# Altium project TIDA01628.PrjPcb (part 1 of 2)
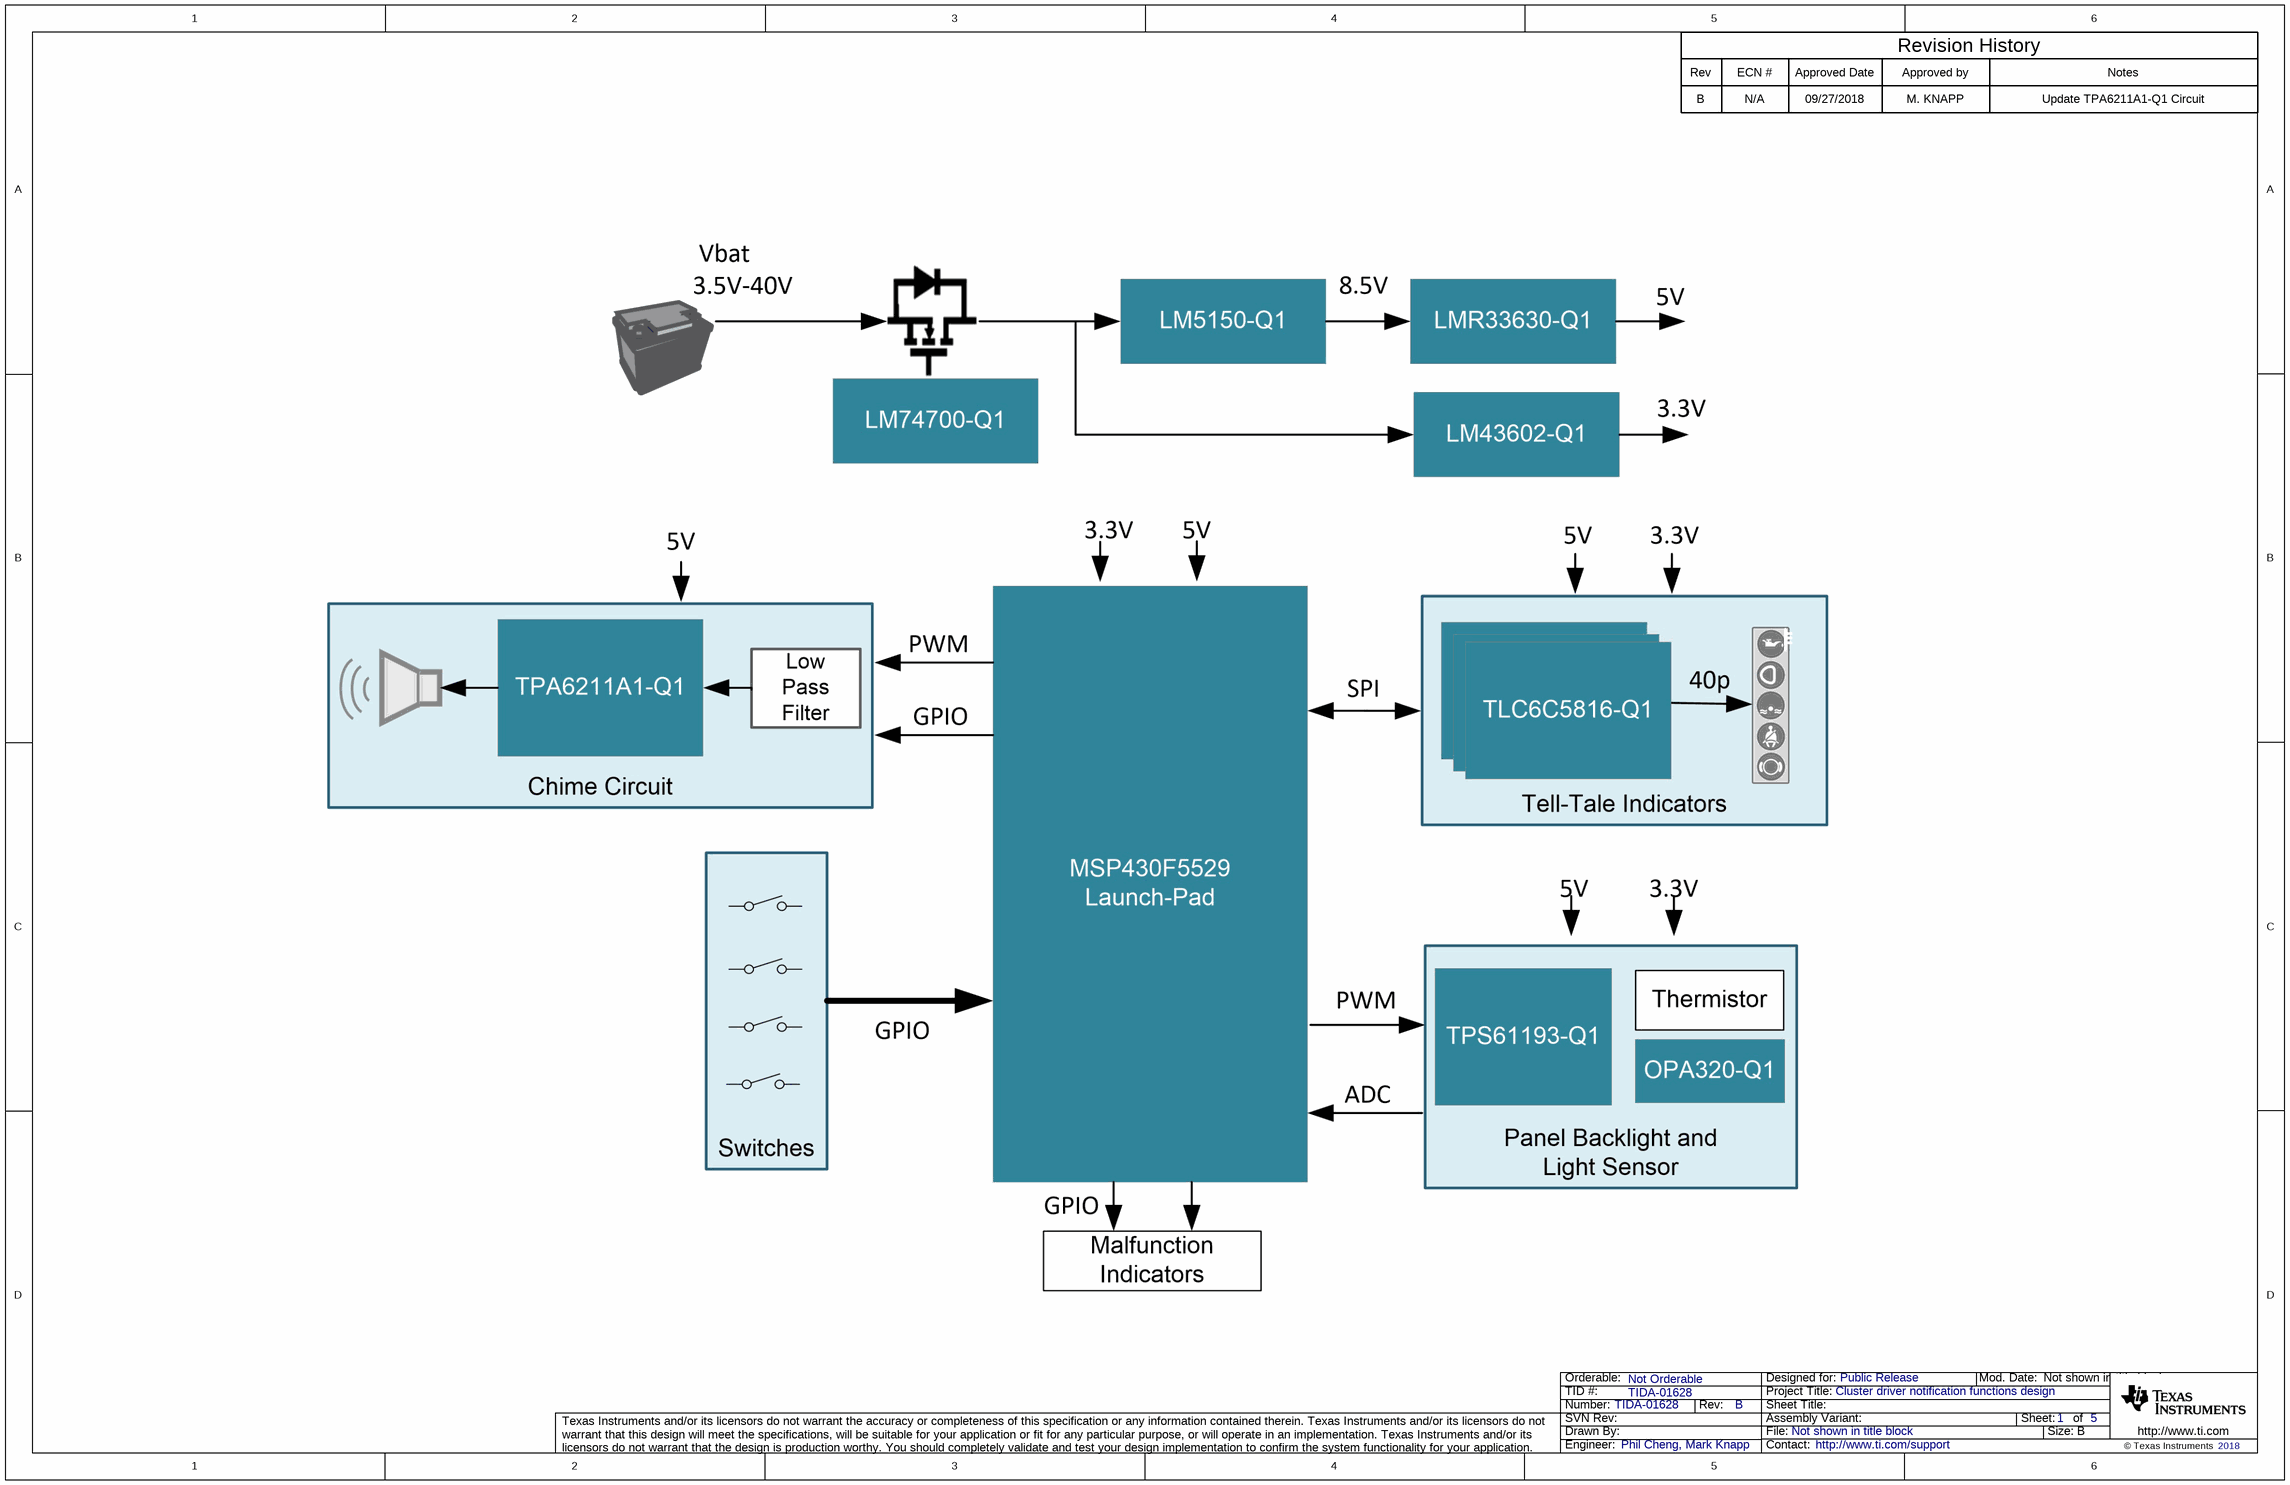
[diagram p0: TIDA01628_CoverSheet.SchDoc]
CopyrightYear: 2018; EVM_orderable: Not Orderable; PCB_Layout: Dee Lim; PCB_Rev: B; PRJ_Customer: Public Release; PRJ_Engineer: Phil Cheng, Mark Knapp; PRJ_Number: TIDA-01628; PRJ_Title: Cluster driver notification functions design; SCH_Rev: B; TechSupport: http://www.ti.com/support; TID: TIDA-01628
5 sheets, 305 parts. Net scope: global (net labels, ports and power ports of the same name join across sheets).
Board file: TIDA01628_PCB.PcbDoc
Sheets:
  TIDA01628_CoverSheet.SchDoc
  TIDA01628_Telltale.SchDoc
  TIDA01628_Power.SchDoc
  TIDA01628_Signal.SchDoc
  TIDA01628_Hardware.SchDoc

## Sheet TIDA01628_CoverSheet.SchDoc
size 431 x 279 mm; Date: Not shown in title block; ApprovedBy: Not shown in title block; CheckedBy: Not shown in title block; Author: Not shown in title block; CompanyName: Not shown in title block; Engineer: Not shown in title block; Organization: Not shown in title block; Address1: Not shown in title block; Address2: Not shown in title block; Address3: Not shown in title block; Address4: Not shown in title block; DocumentNumber: 1; Revision: Use project parameter SCH_Rev; SheetNumber: 1; SheetTotal: 5; PageSetup: Record=PageOptions¦CenterHorizontal=True¦CenterVertical=True¦PrintScale=1.00¦XCorrection=1.00¦YCorrection=1.00¦PrintKind=0¦BorderSize=5000000¦LeftOffset=0¦BottomOffset=0¦Orientation=2¦PaperLength=1000¦PaperWidth=1000¦Scale=100¦PaperSource=15¦PrintQuality=600¦MediaType=1¦DitherType=10¦PaperKind=Letter¦PrintScaleMode=1

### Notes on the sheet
- Rev
- B
- ECN #
- N/A
- Approved Date
- 09/27/2018
- Approved by
- M. KNAPP
- Revision History
- Notes
- Update TPA6211A1-Q1 Circuit

## Sheet TIDA01628_Telltale.SchDoc
size 431 x 279 mm; Date: Not shown in title block; ApprovedBy: Not shown in title block; CheckedBy: Not shown in title block; Author: Not shown in title block; CompanyName: Not shown in title block; Engineer: Not shown in title block; Organization: Not shown in title block; Address1: Not shown in title block; Address2: Not shown in title block; Address3: Not shown in title block; Address4: Not shown in title block; DocumentNumber: 1; Revision: Use project parameter SCH_Rev; SheetNumber: 2; SheetTotal: 5; PageSetup: Record=PageOptions¦CenterHorizontal=True¦CenterVertical=True¦PrintScale=1.00¦XCorrection=1.00¦YCorrection=1.00¦PrintKind=0¦BorderSize=5000000¦LeftOffset=0¦BottomOffset=0¦Orientation=2¦PaperLength=1000¦PaperWidth=1000¦Scale=100¦PaperSource=15¦PrintQuality=600¦MediaType=1¦DitherType=10¦PaperKind=Letter¦PrintScaleMode=1
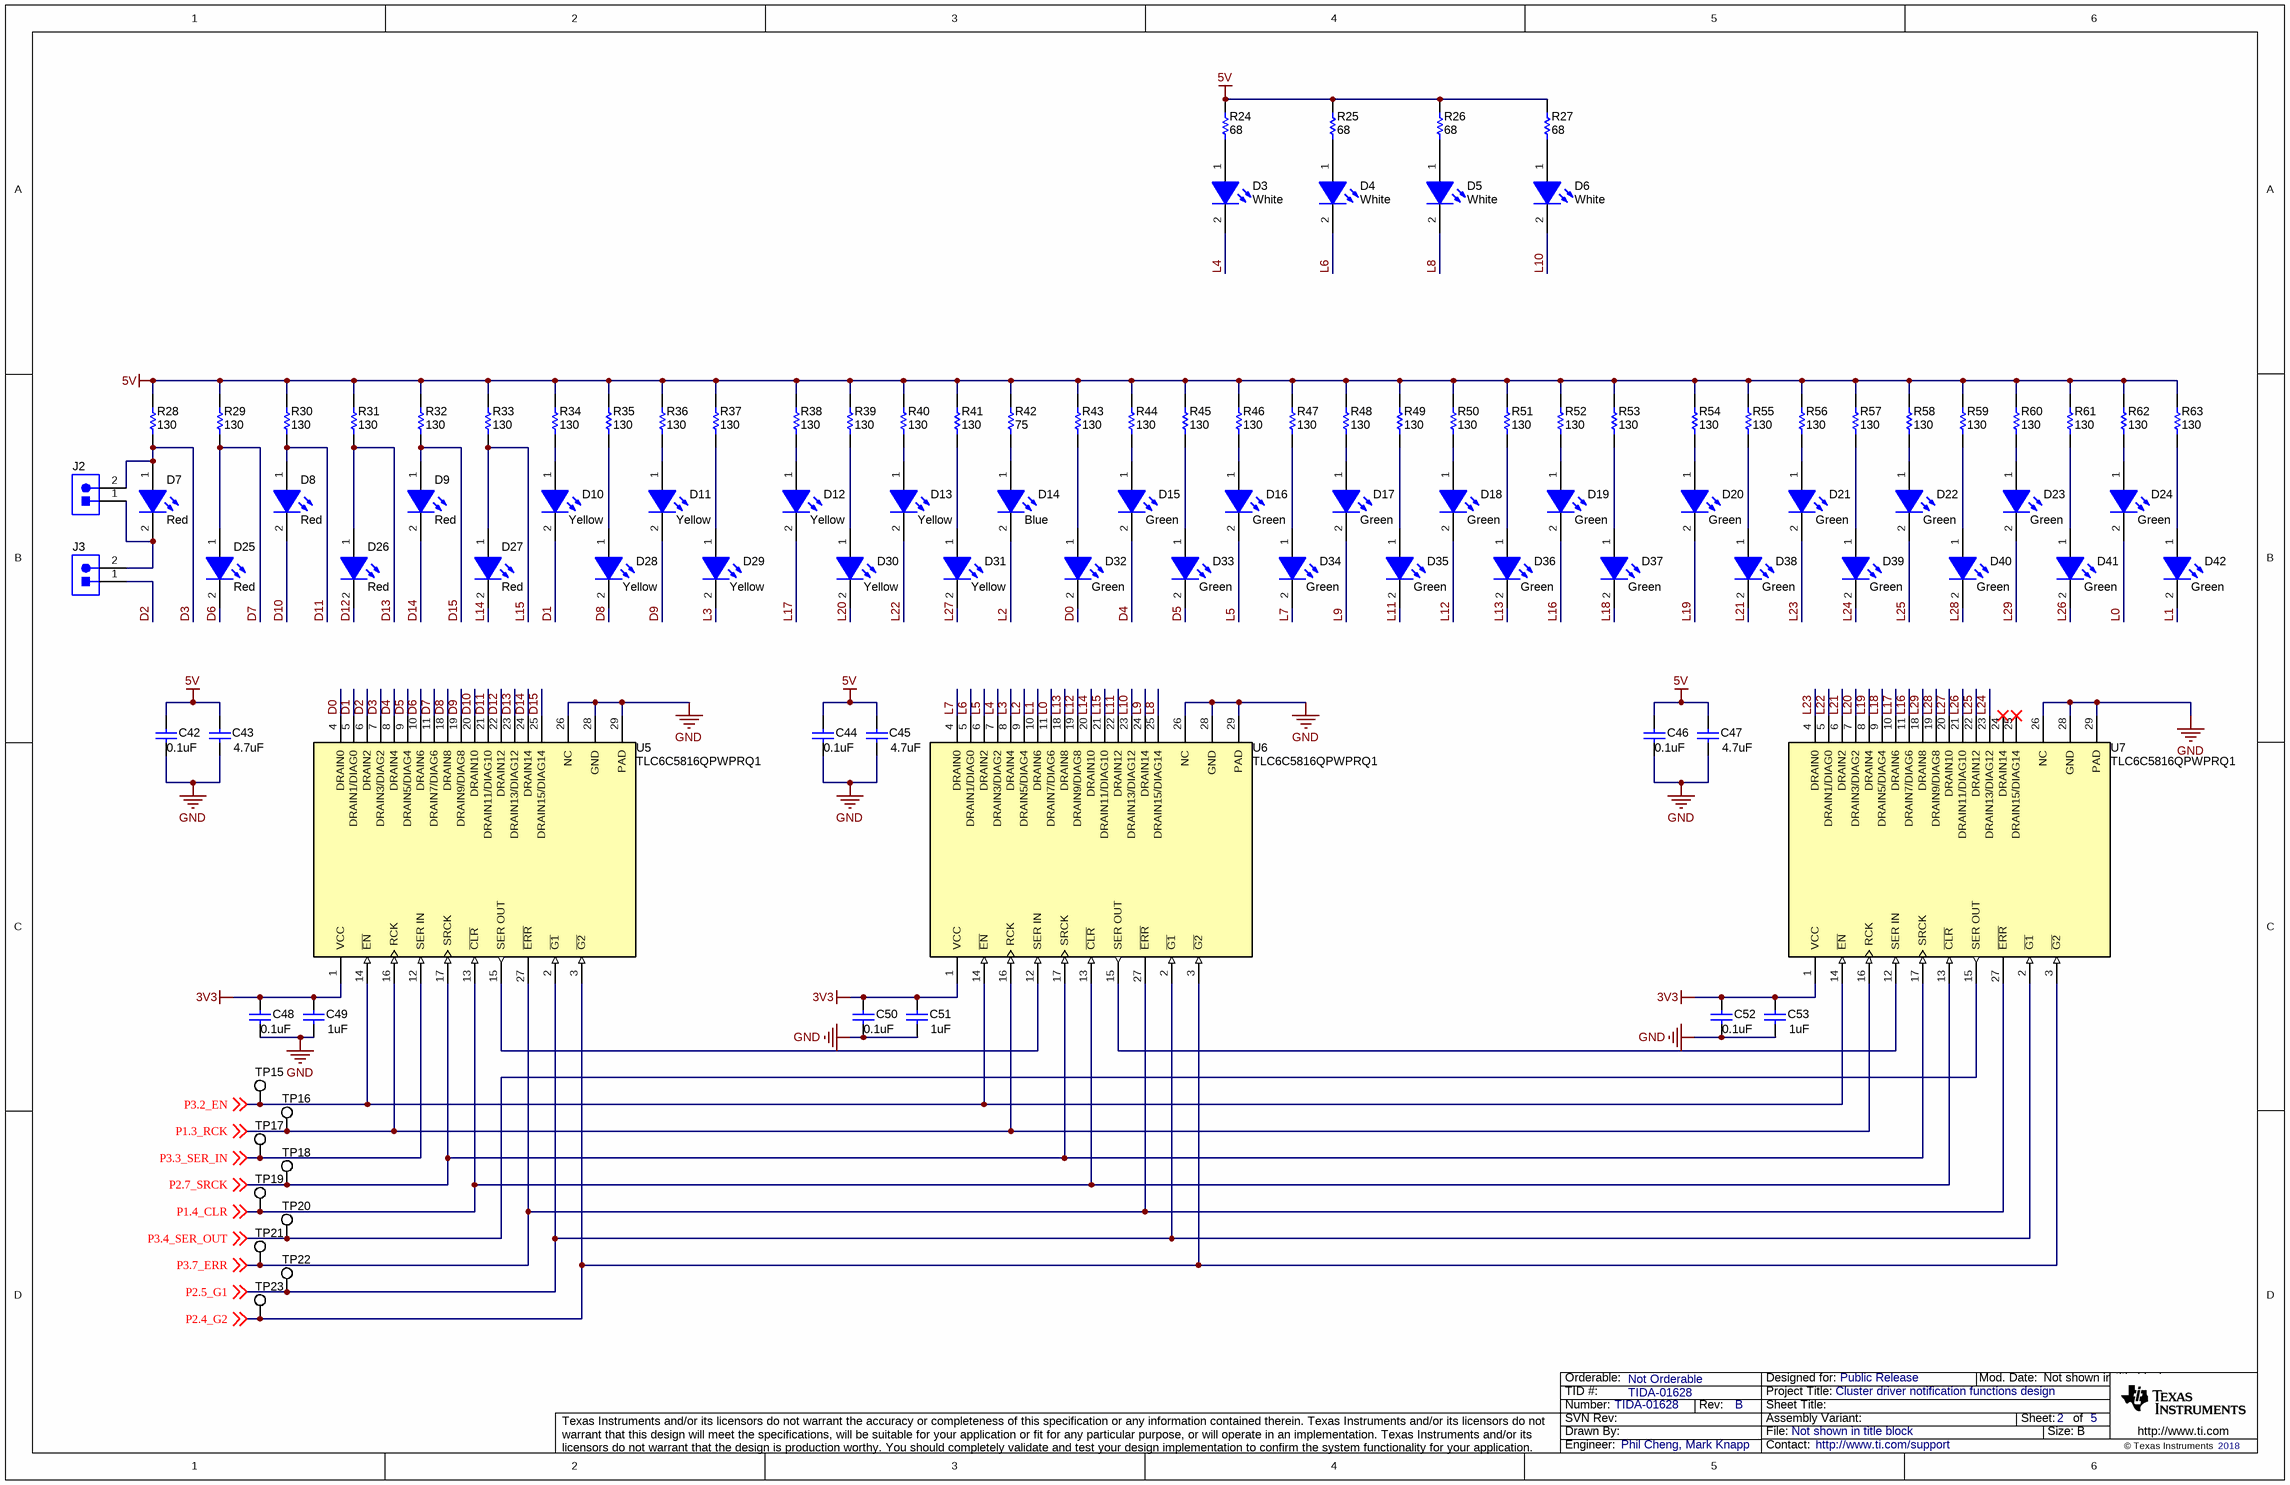
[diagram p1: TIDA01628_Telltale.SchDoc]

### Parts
C42  ValueDisplayed: 0.1uF  [0402]  (hidden comment: GCM155R71H104KE02D)
C43  ValueDisplayed: 4.7uF  [0805_HV]  (hidden comment: GCM21BR71C475KA73K)
C44  ValueDisplayed: 0.1uF  [0402]  (hidden comment: GCM155R71H104KE02D)
C45  ValueDisplayed: 4.7uF  [0805_HV]  (hidden comment: GCM21BR71C475KA73K)
C46  ValueDisplayed: 0.1uF  [0402]  (hidden comment: GCM155R71H104KE02D)
C47  ValueDisplayed: 4.7uF  [0805_HV]  (hidden comment: GCM21BR71C475KA73K)
C48  ValueDisplayed: 0.1uF  [0402]  (hidden comment: GCM155R71H104KE02D)
C49  ValueDisplayed: 1uF  [0603]  (hidden comment: GCM188R71C105KA64D)
C50  ValueDisplayed: 0.1uF  [0402]  (hidden comment: GCM155R71H104KE02D)
C51  ValueDisplayed: 1uF  [0603]  (hidden comment: GCM188R71C105KA64D)
C52  ValueDisplayed: 0.1uF  [0402]  (hidden comment: GCM155R71H104KE02D)
C53  ValueDisplayed: 1uF  [0603]  (hidden comment: GCM188R71C105KA64D)
D3  value White  [KW_DPLS32_EC_White]  (hidden comment: KW DPLS32.EC-6H6J-4F8G-1)
D4  value White  [KW_DPLS32_EC_White]  (hidden comment: KW DPLS32.EC-6H6J-4F8G-1)
D5  value White  [KW_DPLS32_EC_White]  (hidden comment: KW DPLS32.EC-6H6J-4F8G-1)
D6  value White  [KW_DPLS32_EC_White]  (hidden comment: KW DPLS32.EC-6H6J-4F8G-1)
D7  value Red  [LS_T67K_Red]  (hidden comment: LS T67K-J1L2-1-Z)
D8  value Red  [LS_T67K_Red]  (hidden comment: LS T67K-J1L2-1-Z)
D9  value Red  [LS_T67K_Red]  (hidden comment: LS T67K-J1L2-1-Z)
D10  value Yellow  [LY_T67K_Yellow]  (hidden comment: LY T67K-J2M1-26-Z)
D11  value Yellow  [LY_T67K_Yellow]  (hidden comment: LY T67K-J2M1-26-Z)
D12  value Yellow  [LY_T67K_Yellow]  (hidden comment: LY T67K-J2M1-26-Z)
D13  value Yellow  [LY_T67K_Yellow]  (hidden comment: LY T67K-J2M1-26-Z)
D14  value Blue  [LB_T673_Blue]  (hidden comment: LB T673-L2P1-25-Z)
D15  value Green  [LG_T67K_Green]  (hidden comment: LG T67K-G2K1-24-Z)
D16  value Green  [LG_T67K_Green]  (hidden comment: LG T67K-G2K1-24-Z)
D17  value Green  [LG_T67K_Green]  (hidden comment: LG T67K-G2K1-24-Z)
D18  value Green  [LG_T67K_Green]  (hidden comment: LG T67K-G2K1-24-Z)
D19  value Green  [LG_T67K_Green]  (hidden comment: LG T67K-G2K1-24-Z)
D20  value Green  [LG_T67K_Green]  (hidden comment: LG T67K-G2K1-24-Z)
D21  value Green  [LG_T67K_Green]  (hidden comment: LG T67K-G2K1-24-Z)
D22  value Green  [LG_T67K_Green]  (hidden comment: LG T67K-G2K1-24-Z)
D23  value Green  [LG_T67K_Green]  (hidden comment: LG T67K-G2K1-24-Z)
D24  value Green  [LG_T67K_Green]  (hidden comment: LG T67K-G2K1-24-Z)
D25  value Red  [LS_T67K_Red]  (hidden comment: LS T67K-J1L2-1-Z)
D26  value Red  [LS_T67K_Red]  (hidden comment: LS T67K-J1L2-1-Z)
D27  value Red  [LS_T67K_Red]  (hidden comment: LS T67K-J1L2-1-Z)
D28  value Yellow  [LY_T67K_Yellow]  (hidden comment: LY T67K-J2M1-26-Z)
D29  value Yellow  [LY_T67K_Yellow]  (hidden comment: LY T67K-J2M1-26-Z)
D30  value Yellow  [LY_T67K_Yellow]  (hidden comment: LY T67K-J2M1-26-Z)
D31  value Yellow  [LY_T67K_Yellow]  (hidden comment: LY T67K-J2M1-26-Z)
D32  value Green  [LG_T67K_Green]  (hidden comment: LG T67K-G2K1-24-Z)
D33  value Green  [LG_T67K_Green]  (hidden comment: LG T67K-G2K1-24-Z)
D34  value Green  [LG_T67K_Green]  (hidden comment: LG T67K-G2K1-24-Z)
D35  value Green  [LG_T67K_Green]  (hidden comment: LG T67K-G2K1-24-Z)
D36  value Green  [LG_T67K_Green]  (hidden comment: LG T67K-G2K1-24-Z)
D37  value Green  [LG_T67K_Green]  (hidden comment: LG T67K-G2K1-24-Z)
D38  value Green  [LG_T67K_Green]  (hidden comment: LG T67K-G2K1-24-Z)
D39  value Green  [LG_T67K_Green]  (hidden comment: LG T67K-G2K1-24-Z)
D40  value Green  [LG_T67K_Green]  (hidden comment: LG T67K-G2K1-24-Z)
D41  value Green  [LG_T67K_Green]  (hidden comment: LG T67K-G2K1-24-Z)
D42  value Green  [LG_T67K_Green]  (hidden comment: LG T67K-G2K1-24-Z)
J2  PBC02SAAN  [Sullins_PBC02SAAN]  (value not drawn)
J3  PBC02SAAN  [Sullins_PBC02SAAN]  (value not drawn)
R24  ValueDisplayed: 68  [0603]  (hidden comment: CRCW060368R0JNEA)
R25  ValueDisplayed: 68  [0603]  (hidden comment: CRCW060368R0JNEA)
R26  ValueDisplayed: 68  [0603]  (hidden comment: CRCW060368R0JNEA)
R27  ValueDisplayed: 68  [0603]  (hidden comment: CRCW060368R0JNEA)
R28  ValueDisplayed: 130  [0603]  (hidden comment: CRCW0603130RFKEA)
R29  ValueDisplayed: 130  [0603]  (hidden comment: CRCW0603130RFKEA)
R30  ValueDisplayed: 130  [0603]  (hidden comment: CRCW0603130RFKEA)
R31  ValueDisplayed: 130  [0603]  (hidden comment: CRCW0603130RFKEA)
R32  ValueDisplayed: 130  [0603]  (hidden comment: CRCW0603130RFKEA)
R33  ValueDisplayed: 130  [0603]  (hidden comment: CRCW0603130RFKEA)
R34  ValueDisplayed: 130  [0603]  (hidden comment: CRCW0603130RFKEA)
R35  ValueDisplayed: 130  [0603]  (hidden comment: CRCW0603130RFKEA)
R36  ValueDisplayed: 130  [0603]  (hidden comment: CRCW0603130RFKEA)
R37  ValueDisplayed: 130  [0603]  (hidden comment: CRCW0603130RFKEA)
R38  ValueDisplayed: 130  [0603]  (hidden comment: CRCW0603130RFKEA)
R39  ValueDisplayed: 130  [0603]  (hidden comment: CRCW0603130RFKEA)
R40  ValueDisplayed: 130  [0603]  (hidden comment: CRCW0603130RFKEA)
R41  ValueDisplayed: 130  [0603]  (hidden comment: CRCW0603130RFKEA)
R42  ValueDisplayed: 75  [0603]  (hidden comment: CRCW060375R0JNEA)
R43  ValueDisplayed: 130  [0603]  (hidden comment: CRCW0603130RFKEA)
R44  ValueDisplayed: 130  [0603]  (hidden comment: CRCW0603130RFKEA)
R45  ValueDisplayed: 130  [0603]  (hidden comment: CRCW0603130RFKEA)
R46  ValueDisplayed: 130  [0603]  (hidden comment: CRCW0603130RFKEA)
R47  ValueDisplayed: 130  [0603]  (hidden comment: CRCW0603130RFKEA)
R48  ValueDisplayed: 130  [0603]  (hidden comment: CRCW0603130RFKEA)
R49  ValueDisplayed: 130  [0603]  (hidden comment: CRCW0603130RFKEA)
R50  ValueDisplayed: 130  [0603]  (hidden comment: CRCW0603130RFKEA)
R51  ValueDisplayed: 130  [0603]  (hidden comment: CRCW0603130RFKEA)
R52  ValueDisplayed: 130  [0603]  (hidden comment: CRCW0603130RFKEA)
R53  ValueDisplayed: 130  [0603]  (hidden comment: CRCW0603130RFKEA)
R54  ValueDisplayed: 130  [0603]  (hidden comment: CRCW0603130RFKEA)
R55  ValueDisplayed: 130  [0603]  (hidden comment: CRCW0603130RFKEA)
R56  ValueDisplayed: 130  [0603]  (hidden comment: CRCW0603130RFKEA)
R57  ValueDisplayed: 130  [0603]  (hidden comment: CRCW0603130RFKEA)
R58  ValueDisplayed: 130  [0603]  (hidden comment: CRCW0603130RFKEA)
R59  ValueDisplayed: 130  [0603]  (hidden comment: CRCW0603130RFKEA)
R60  ValueDisplayed: 130  [0603]  (hidden comment: CRCW0603130RFKEA)
R61  ValueDisplayed: 130  [0603]  (hidden comment: CRCW0603130RFKEA)
R62  ValueDisplayed: 130  [0603]  (hidden comment: CRCW0603130RFKEA)
R63  ValueDisplayed: 130  [0603]  (hidden comment: CRCW0603130RFKEA)
TP15  5002  [Keystone5002]  (value not drawn)
TP16  5002  [Keystone5002]  (value not drawn)
TP17  5002  [Keystone5002]  (value not drawn)
TP18  5002  [Keystone5002]  (value not drawn)
TP19  5002  [Keystone5002]  (value not drawn)
TP20  5002  [Keystone5002]  (value not drawn)
TP21  5002  [Keystone5002]  (value not drawn)
TP22  5002  [Keystone5002]  (value not drawn)
TP23  5002  [Keystone5002]  (value not drawn)
U5  TLC6C5816QPWPRQ1  [PWP0028C_N]
U6  TLC6C5816QPWPRQ1  [PWP0028C_N]
U7  TLC6C5816QPWPRQ1  [PWP0028C_N]

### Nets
3V3: C48.1 C49.1 C50.1 C51.1 C52.1 C53.1 U5.1(VCC) U6.1(VCC) U7.1(VCC)
5V: C42.1 C43.1 C44.1 C45.1 C46.1 C47.1 R24.2 R25.2 R26.2 R27.2 R28.2 R29.2 R30.2 R31.2 R32.2 R33.2 R34.2 R35.2 R36.2 R37.2 R38.2 R39.2 R40.2 R41.2 R42.2 R43.2 R44.2 R45.2 R46.2 R47.2 R48.2 R49.2 R50.2 R51.2 R52.2 R53.2 R54.2 R55.2 R56.2 R57.2 R58.2 R59.2 R60.2 R61.2 R62.2 R63.2
GND: C42.2 C43.2 C44.2 C45.2 C46.2 C47.2 C48.2 C49.2 C50.2 C51.2 C52.2 C53.2 U5.26(NC) U5.28(GND) U5.29(PAD) U6.26(NC) U6.28(GND) U6.29(PAD) U7.26(NC) U7.28(GND) U7.29(PAD)
D0: D32.2(K) U5.4(DRAIN0)
D1: D10.2(K) U5.5(DRAIN1/DIAG0)
D2: J3.1 U5.6(DRAIN2)
D3: D7.1(A) J2.2 R28.1 U5.7(DRAIN3/DIAG2)
D4: D15.2(K) U5.8(DRAIN4)
D5: D33.2(K) U5.9(DRAIN5/DIAG4)
D6: D25.2(K) U5.10(DRAIN6)
D7: D25.1(A) R29.1 U5.11(DRAIN7/DIAG6)
D8: D28.2(K) U5.18(DRAIN8)
D9: D11.2(K) U5.19(DRAIN9/DIAG8)
D10: D8.2(K) U5.20(DRAIN10)
D11: D8.1(A) R30.1 U5.21(DRAIN11/DIAG10)
D12: D26.2(K) U5.22(DRAIN12)
D13: D26.1(A) R31.1 U5.23(DRAIN13/DIAG12)
D14: D9.2(K) U5.24(DRAIN14)
D15: D9.1(A) R32.1 U5.25(DRAIN15/DIAG14)
L0: D24.2(K) U6.11(DRAIN7/DIAG6)
L1: D42.2(K) U6.10(DRAIN6)
L2: D14.2(K) U6.9(DRAIN5/DIAG4)
L3: D29.2(K) U6.8(DRAIN4)
L4: D3.2(K) U6.7(DRAIN3/DIAG2)
L5: D16.2(K) U6.6(DRAIN2)
L6: D4.2(K) U6.5(DRAIN1/DIAG0)
L7: D34.2(K) U6.4(DRAIN0)
L8: D5.2(K) U6.25(DRAIN15/DIAG14)
L9: D17.2(K) U6.24(DRAIN14)
L10: D6.2(K) U6.23(DRAIN13/DIAG12)
L11: D35.2(K) U6.22(DRAIN12)
L12: D18.2(K) U6.19(DRAIN9/DIAG8)
L13: D36.2(K) U6.18(DRAIN8)
L14: D27.2(K) U6.20(DRAIN10)
L15: D27.1(A) R33.1 U6.21(DRAIN11/DIAG10)
L16: D19.2(K) U7.11(DRAIN7/DIAG6)
L17: D12.2(K) U7.10(DRAIN6)
L18: D37.2(K) U7.9(DRAIN5/DIAG4)
L19: D20.2(K) U7.8(DRAIN4)
L20: D30.2(K) U7.7(DRAIN3/DIAG2)
L21: D38.2(K) U7.6(DRAIN2)
L22: D13.2(K) U7.5(DRAIN1/DIAG0)
L23: D21.2(K) U7.4(DRAIN0)
L24: D39.2(K) U7.23(DRAIN13/DIAG12)
L25: D22.2(K) U7.22(DRAIN12)
L26: D41.2(K) U7.21(DRAIN11/DIAG10)
L27: D31.2(K) U7.20(DRAIN10)
L28: D40.2(K) U7.19(DRAIN9/DIAG8)
L29: D23.2(K) U7.18(DRAIN8)
P1.3_RCK: TP16.1 U5.16(RCK) U6.16(RCK) U7.16(RCK) ; off-sheet P1.3_RCK
P1.4_CLR: TP19.1 U5.13(~{CLR}) U6.13(~{CLR}) U7.13(~{CLR}) ; off-sheet P1.4_CLR
P2.4_G2: TP23.1 U5.3(~{G2}) U6.3(~{G2}) U7.3(~{G2}) ; off-sheet P2.4_G2
P2.5_G1: TP22.1 U5.2(~{G1}) U6.2(~{G1}) U7.2(~{G1}) ; off-sheet P2.5_G1
P2.7_SRCK: TP18.1 U5.17(SRCK) U6.17(SRCK) U7.17(SRCK) ; off-sheet P2.7_SRCK
P3.2_EN: TP15.1 U5.14(~{EN}) U6.14(~{EN}) U7.14(~{EN}) ; off-sheet P3.2_EN
P3.3_SER_IN: TP17.1 U5.12(SER_IN) ; off-sheet P3.3_SER_IN
P3.4_SER_OUT: TP20.1 U7.15(SER_OUT) ; off-sheet P3.4_SER_OUT  [project net P3.4]
P3.7_ERR: TP21.1 U5.27(~{ERR}) U6.27(~{ERR}) U7.27(~{ERR}) ; off-sheet P3.7_ERR
NetD3_1: D3.1(A) R24.1
NetD4_1: D4.1(A) R25.1
NetD5_1: D5.1(A) R26.1
NetD6_1: D6.1(A) R27.1
NetD7_2: D7.2(K) J2.1 J3.2
NetD10_1: D10.1(A) R34.1
NetD11_1: D11.1(A) R36.1
NetD12_1: D12.1(A) R38.1
NetD13_1: D13.1(A) R40.1
NetD14_1: D14.1(A) R42.1
NetD15_1: D15.1(A) R44.1
NetD16_1: D16.1(A) R46.1
NetD17_1: D17.1(A) R48.1
NetD18_1: D18.1(A) R50.1
NetD19_1: D19.1(A) R52.1
NetD20_1: D20.1(A) R54.1
NetD21_1: D21.1(A) R56.1
NetD22_1: D22.1(A) R58.1
NetD23_1: D23.1(A) R60.1
NetD24_1: D24.1(A) R62.1
NetD28_1: D28.1(A) R35.1
NetD29_1: D29.1(A) R37.1
NetD30_1: D30.1(A) R39.1
NetD31_1: D31.1(A) R41.1
NetD32_1: D32.1(A) R43.1
NetD33_1: D33.1(A) R45.1
NetD34_1: D34.1(A) R47.1
NetD35_1: D35.1(A) R49.1
NetD36_1: D36.1(A) R51.1
NetD37_1: D37.1(A) R53.1
NetD38_1: D38.1(A) R55.1
NetD39_1: D39.1(A) R57.1
NetD40_1: D40.1(A) R59.1
NetD41_1: D41.1(A) R61.1
NetD42_1: D42.1(A) R63.1
NetU5_15: U5.15(SER_OUT) U6.12(SER_IN)
NetU6_15: U6.15(SER_OUT) U7.12(SER_IN)

Not connected (* = marked no-connect by the designer): U7 24(DRAIN14)* 25(DRAIN15/DIAG14)*

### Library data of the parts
C42 C44 C46 C48 C50 C52 = CMP-0006356-2: CAP, CERM, 0.1 uF, 50 V, +/- 10%, X7R, AEC-Q200 Grade 1, 0402; Manufacturer: MuRata; TaMin_C: -55°C; Polarized: N; SizeAreaWB_mm2: 3; Value1: Unknown; U/M: EA; Value: 0.1uF; TaMax_C: 125°C; SizeZ_mm: 0.6; SizeX_mm: 1; SizeY_mm: 0.5; Value2: 50V; CompType: Capacitor; AEC Qualified: Y; Cap_F: 100nF; AEC Category: Q200
C43 C45 C47 = CMP-0008019-2: CAP, CERM, 4.7 uF, 16 V, +/- 10%, X7R, AEC-Q200 Grade 1, 0805; Manufacturer: MuRata; TaMin_C: -55°C; Polarized: N; SizeAreaWB_mm2: 6.75; Value1: Unknown; U/M: EA; Value: 4.7uF; TaMax_C: 125°C; SizeZ_mm: 1.45; SizeX_mm: 2; SizeY_mm: 1.25; Cap_Case: 0805; Value2: 16V; SizeArea_mm2: 2.5; CompType: Capacitor; AEC Qualified: Y; Cap_F: 4.7µF; AEC Grade: 1; AEC Category: Q200
C49 C51 C53 = CMP-0007136-5: CAP, CERM, 1 uF, 16 V, +/- 10%, X7R, AEC-Q200 Grade 1, 0603; Manufacturer: MuRata; TaMin_C: -55°C; Polarized: N; SizeAreaWB_mm2: 4.68; Value1: Unknown; U/M: EA; Value: 1uF; TaMax_C: 125°C; SizeZ_mm: 1; SizeX_mm: 1.6; SizeY_mm: 0.8; Value2: 16V; SizeArea_mm2: 1.28; CompType: Capacitor; AEC Qualified: Y; Cap_F: 1µF; AEC Category: Q200
D3-D6 = KW DPLS32.EC-6H6J-4F8G-1: LED, White, SMD; Manufacturer: OSRAM; Type: InGaN; Vf_V: 3.15; Value2: 3.15V; Io_A: 0.12; Tjmax_C: 125; Value1: W; Angle: 120; SizeAreaWB_mm2: 12; SizeArea_mm2: 5.6; SizeX_mm: 4; SizeY_mm: 1.4; SizeZ_mm: 0.75; U/M: EA
D7-D9 D25-D27 = CMP-0003010-2: LED, Super Red, SMD; Manufacturer: OSRAM; Io_A: 20mA; SizeAreaWB_mm2: 17.1; Vr_V: 12V; Tjmax_C: 125°C; Value1: W; U/M: EA; Angle: 120; SizeZ_mm: 2.1; SizeX_mm: 2.8; SizeY_mm: 3.5; Ir_A: 10µA; Vf_V: 1.8V; SizeArea_mm2: 9.8; Type: AlInGaP
D10-D13 D28-D31 = CMP-0003012-2: LED, Yellow, SMD; Manufacturer: OSRAM; Io_A: 20mA; SizeAreaWB_mm2: 17.1; Vr_V: 12V; Tjmax_C: 125°C; Value1: W; U/M: EA; Angle: 120; SizeZ_mm: 2.1; SizeX_mm: 2.8; SizeY_mm: 3.5; Ir_A: 10µA; Vf_V: 1.8V; SizeArea_mm2: 9.8; Type: AlInGaP
D14 = CMP-0003013-2: LED, Blue, SMD; Manufacturer: OSRAM; Io_A: 20mA; SizeAreaWB_mm2: 17.1; Vr_V: 5V; Tjmax_C: 110°C; Value1: W; U/M: EA; Angle: 120; SizeZ_mm: 2.1; SizeX_mm: 2.8; SizeY_mm: 3.5; Ir_A: 10µA; Vf_V: 3.1V; SizeArea_mm2: 9.8; Type: InGaN
D15-D24 D32-D42 = CMP-0003009-2: LED, Green, SMD; Manufacturer: OSRAM; Io_A: 20mA; SizeAreaWB_mm2: 17.1; Vr_V: 12V; Tjmax_C: 125°C; Value1: W; U/M: EA; Angle: 120; SizeZ_mm: 2.1; SizeX_mm: 2.8; SizeY_mm: 3.5; Ir_A: 10µA; Vf_V: 1.8V; SizeArea_mm2: 9.8; Type: AlInGaP
J2 J3 = CMP-0054566-1: Header, 100mil, 2x1, Gold, TH; Manufacturer: Sullins Connector Solutions; CNHeader: TRUE; Current_A: 3A; Green_Lifecycle: Active; Shrouded: N; Gender: Male; Green_REACh: Passed; Voltage_V: 1.8kV; Row_Count: 1; Pitch_mm: 2.54; CT: FALSE; Cert_UL: Y
R24-R27 = CMP-0025843-4: RES, 68, 5%, 0.1 W, AEC-Q200 Grade 0, 0603; Manufacturer: Vishay-Dale; Power_W: 100mW; TempCo: 200 ppm/C; Value_Code: 68R0; Value: 68; EIA_Code: E24; SizeX_mm: 1.6; SizeY_mm: 0.8; SizeZ_mm: 1; Value2: 0.1W; SizeArea_mm2: 1.28; AEC Qualified: Y; VDC_V: 75V; AEC Category: Q200; AEC Grade: 0
R28-R41 R43-R63 = CMP-0022037-5: RES, 130, 1%, 0.1 W, AEC-Q200 Grade 0, 0603; Manufacturer: Vishay-Dale; Power_W: 100mW; TempCo: 100 ppm/C; Value_Code: 130R; Value: 130; EIA_Code: E96; SizeX_mm: 1.6; SizeY_mm: 0.8; SizeZ_mm: 1; Value2: 0.1W; SizeArea_mm2: 1.28; CompType: Resistor; AEC Qualified: Y; VDC_V: 75V; AEC Category: Q200; AEC Grade: 0
R42 = CMP-0025854-4: RES, 75, 5%, 0.1 W, AEC-Q200 Grade 0, 0603; Manufacturer: Vishay-Dale; Power_W: 100mW; TempCo: 200 ppm/C; Value_Code: 75R0; Value: 75; EIA_Code: E24; SizeX_mm: 1.6; SizeY_mm: 0.8; SizeZ_mm: 1; Value2: 0.1W; SizeArea_mm2: 1.28; CompType: Resistor; AEC Qualified: Y; VDC_V: 75V; AEC Category: Q200; AEC Grade: 0
TP15-TP23 = CMP-0055139-1: Test Point, Miniature, White, TH; Manufacturer: Keystone; CNHeader: FALSE; Green_Lifecycle: Active; Green_REACh: Passed; ContactFinish: Silver; CT: TRUE
U5-U7 = CMP-0013686-4: Power Logic 16-Bit Shift Register LED Driver with Diagnostic, PWP0028C (TSSOP-28); Manufacturer: Texas Instruments; SizeX_mm: 6.4; SizeY_mm: 9.7; CompType: IC; SizeZ_mm: 1.2; SizeArea_mm2: 62.08; SizeAreaWB_mm2: 98.28; U/M: EA

## Sheet TIDA01628_Power.SchDoc
size 431 x 279 mm; Date: Not shown in title block; ApprovedBy: Not shown in title block; CheckedBy: Not shown in title block; Author: Not shown in title block; CompanyName: Not shown in title block; Engineer: Not shown in title block; Organization: Not shown in title block; Address1: Not shown in title block; Address2: Not shown in title block; Address3: Not shown in title block; Address4: Not shown in title block; DocumentNumber: 1; Revision: Use project parameter SCH_Rev; SheetNumber: 3; SheetTotal: 5; PageSetup: Record=PageOptions¦CenterHorizontal=True¦CenterVertical=True¦PrintScale=1.00¦XCorrection=1.00¦YCorrection=1.00¦PrintKind=0¦BorderSize=5000000¦LeftOffset=0¦BottomOffset=0¦Orientation=2¦PaperLength=1000¦PaperWidth=1000¦Scale=100¦PaperSource=15¦PrintQuality=600¦MediaType=1¦DitherType=10¦PaperKind=Letter¦PrintScaleMode=1
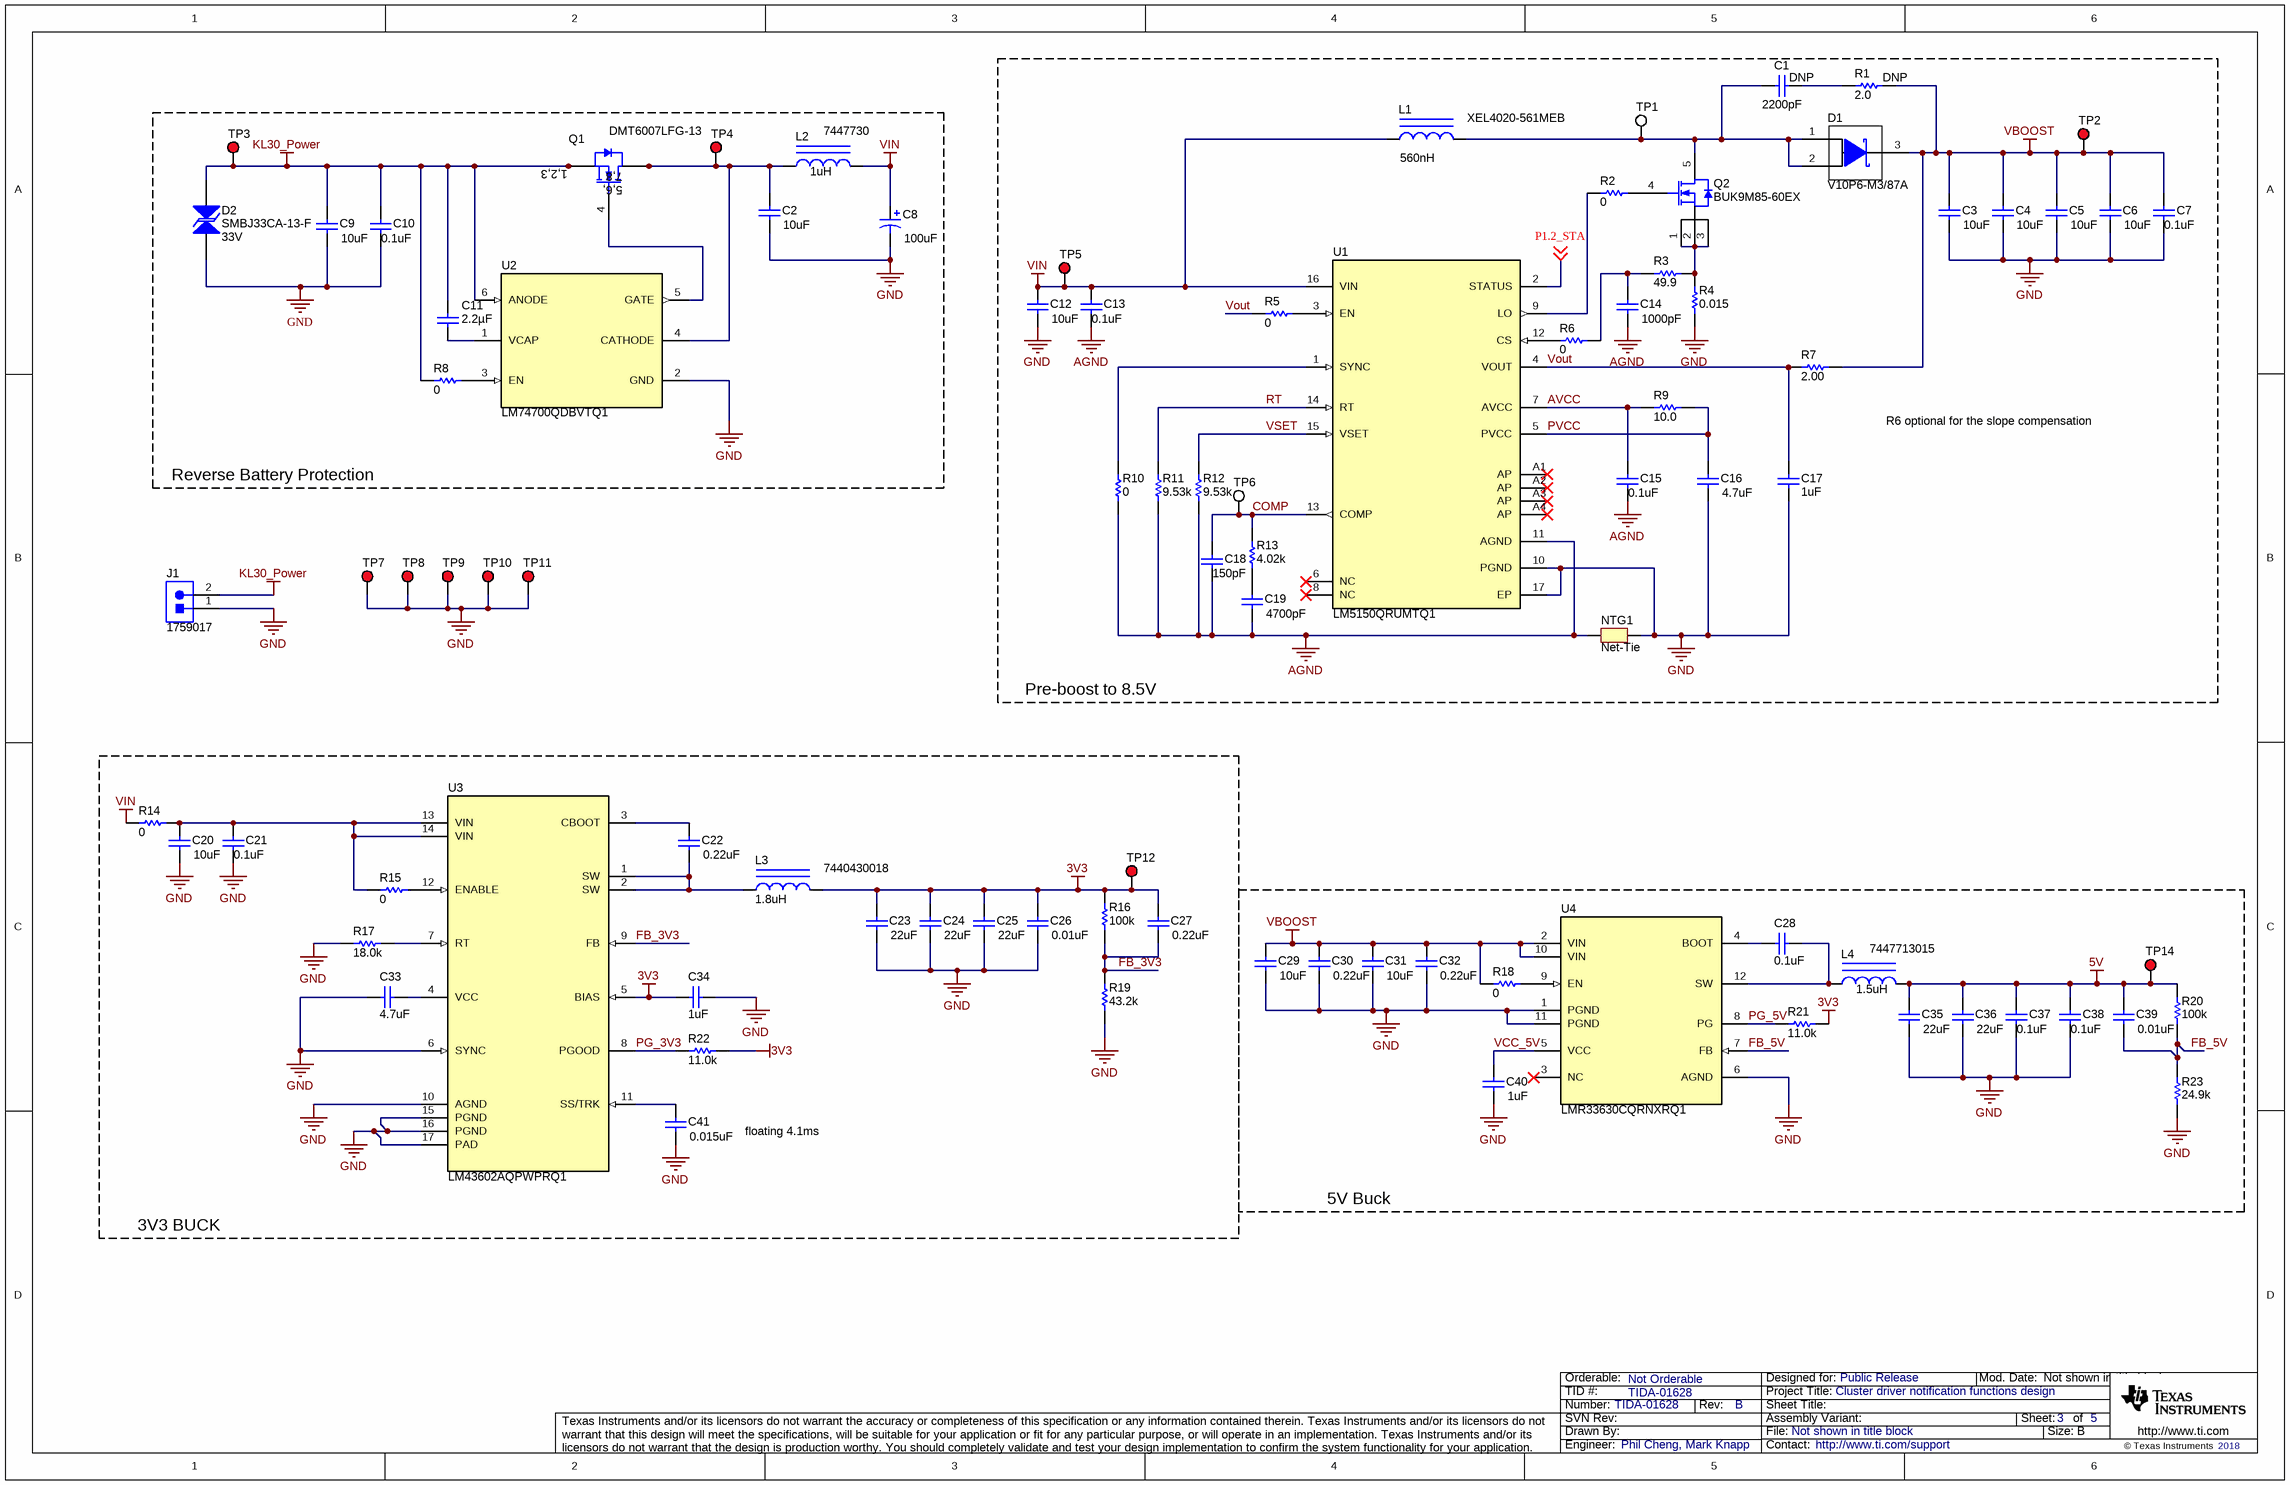
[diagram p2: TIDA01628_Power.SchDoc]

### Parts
C1  DNP  ValueDisplayed: 2200pF  [0402]
C2  ValueDisplayed: 10uF  [1210_280]  (hidden comment: UMK325AB7106KMHT)
C3  ValueDisplayed: 10uF  [1210_280]  (hidden comment: UMK325AB7106KMHT)
C4  ValueDisplayed: 10uF  [1210_280]  (hidden comment: UMK325AB7106KMHT)
C5  ValueDisplayed: 10uF  [1210_280]  (hidden comment: UMK325AB7106KMHT)
C6  ValueDisplayed: 10uF  [1210_280]  (hidden comment: UMK325AB7106KMHT)
C7  ValueDisplayed: 0.1uF  [0402]  (hidden comment: GCM155R71H104KE02D)
C8  ValueDisplayed: 100uF  [SM_RADIAL_F]  (hidden comment: EEE-FK1H101P)
C9  ValueDisplayed: 10uF  [1210_280]  (hidden comment: UMK325AB7106KMHT)
C10  ValueDisplayed: 0.1uF  [0402]  (hidden comment: GCM155R71H104KE02D)
C11  ValueDisplayed: 2.2µF  [0805_HV]  (hidden comment: C2012X5R1H225K125AB)
C12  ValueDisplayed: 10uF  [1210_280]  (hidden comment: UMK325AB7106KMHT)
C13  ValueDisplayed: 0.1uF  [0402]  (hidden comment: GCM155R71H104KE02D)
C14  ValueDisplayed: 1000pF  [0402]  (hidden comment: GRM155R71H102KA01D)
C15  ValueDisplayed: 0.1uF  [0402]  (hidden comment: GCM155R71H104KE02D)
C16  ValueDisplayed: 4.7uF  [0805_HV]  (hidden comment: GCM21BR71C475KA73K)
C17  ValueDisplayed: 1uF  [0603]  (hidden comment: GCM188R71C105KA64D)
C18  ValueDisplayed: 150pF  [0402]  (hidden comment: CGA2B2C0G1H151J050BA)
C19  ValueDisplayed: 4700pF  [0402]  (hidden comment: CGA2B2X7R1H472K050BA)
C20  ValueDisplayed: 10uF  [1210_280]  (hidden comment: UMK325AB7106KMHT)
C21  ValueDisplayed: 0.1uF  [0402]  (hidden comment: GCM155R71H104KE02D)
C22  ValueDisplayed: 0.22uF  [0603]  (hidden comment: CGA3E3X7R1H224K080AB)
C23  ValueDisplayed: 22uF  [1210_280]  (hidden comment: CGA6P1X7R1C226M250AC)
C24  ValueDisplayed: 22uF  [1210_280]  (hidden comment: CGA6P1X7R1C226M250AC)
C25  ValueDisplayed: 22uF  [1210_280]  (hidden comment: CGA6P1X7R1C226M250AC)
C26  ValueDisplayed: 0.01uF  [0402]  (hidden comment: CGA2B3X7R1H103K050BB)
C27  ValueDisplayed: 0.22uF  [0603]  (hidden comment: CGA3E3X7R1H224K080AB)
C28  ValueDisplayed: 0.1uF  [0402]  (hidden comment: GCM155R71H104KE02D)
C29  ValueDisplayed: 10uF  [1210_280]  (hidden comment: UMK325AB7106KMHT)
C30  ValueDisplayed: 0.22uF  [0603]  (hidden comment: CGA3E3X7R1H224K080AB)
C31  ValueDisplayed: 10uF  [1210_280]  (hidden comment: UMK325AB7106KMHT)
C32  ValueDisplayed: 0.22uF  [0603]  (hidden comment: CGA3E3X7R1H224K080AB)
C33  ValueDisplayed: 4.7uF  [0805_HV]  (hidden comment: GCM21BR71C475KA73K)
C34  ValueDisplayed: 1uF  [0603]  (hidden comment: GCM188R71C105KA64D)
C35  ValueDisplayed: 22uF  [1210_280]  (hidden comment: CGA6P1X7R1C226M250AC)
C36  ValueDisplayed: 22uF  [1210_280]  (hidden comment: CGA6P1X7R1C226M250AC)
C37  ValueDisplayed: 0.1uF  [0402]  (hidden comment: GCM155R71H104KE02D)
C38  ValueDisplayed: 0.1uF  [0402]  (hidden comment: GCM155R71H104KE02D)
C39  ValueDisplayed: 0.01uF  [0402]  (hidden comment: CGA2B3X7R1H103K050BB)
C40  ValueDisplayed: 1uF  [0603]  (hidden comment: GCM188R71C105KA64D)
C41  ValueDisplayed: 0.015uF  [0402]  (hidden comment: CGA2B3X7R1H153K050BB)
D1  V10P6-M3/87A  [TO-277A]
D2  SMBJ33CA-13-F  value 33V  [SMB]
J1  1759017  [Phoenix_1759017]
L1  XEL4020-561MEB  ValueDisplayed: 560nH  [XEL4020]
L2  7447730  ValueDisplayed: 1uH  [WE-PD2-S]
L3  7440430018  ValueDisplayed: 1.8uH  [WE-TPC_4828]
L4  7447713015  ValueDisplayed: 1.5uH  [WE-PD_1030]
NTG1  Net-Tie  [Net-Tie_50milWide_30milLong]  (net tie, no BOM)
Q1  DMT6007LFG-13  [PowerDI3333-8]
Q2  BUK9M85-60EX  [TRANS_NXP_LFPAK33]
R1  DNP  ValueDisplayed: 2.0  [2010]
R2  ValueDisplayed: 0  [0402]  (hidden comment: CRCW04020000Z0ED)
R3  ValueDisplayed: 49.9  [0402]  (hidden comment: CRCW040249R9FKED)
R4  ValueDisplayed: 0.015  [1206]  (hidden comment: WSLP1206R0150FEA)
R5  ValueDisplayed: 0  [0402]  (hidden comment: CRCW04020000Z0ED)
R6  ValueDisplayed: 0  [0402]  (hidden comment: CRCW04020000Z0ED)
R7  ValueDisplayed: 2.00  [0603]  (hidden comment: RC0603FR-072RL)
R8  ValueDisplayed: 0  [0402]  (hidden comment: CRCW04020000Z0ED)
R9  ValueDisplayed: 10.0  [0402]  (hidden comment: CRCW040210R0FKED)
R10  ValueDisplayed: 0  [0402]  (hidden comment: CRCW04020000Z0ED)
R11  ValueDisplayed: 9.53k  [0603]  (hidden comment: CRCW06039K53FKEA)
R12  ValueDisplayed: 9.53k  [0603]  (hidden comment: CRCW06039K53FKEA)
R13  ValueDisplayed: 4.02k  [0402]  (hidden comment: CRCW04024K02FKED)
R14  ValueDisplayed: 0  [1206]  (hidden comment: CRCW12060000Z0EA)
R15  ValueDisplayed: 0  [0402]  (hidden comment: CRCW04020000Z0ED)
R16  ValueDisplayed: 100k  [0402]  (hidden comment: CRCW0402100KFKED)
R17  ValueDisplayed: 18.0k  [0402]  (hidden comment: CRCW040218K0FKED)
R18  ValueDisplayed: 0  [0402]  (hidden comment: CRCW04020000Z0ED)
R19  ValueDisplayed: 43.2k  [0402]  (hidden comment: CRCW040243K2FKED)
R20  ValueDisplayed: 100k  [0402]  (hidden comment: CRCW0402100KFKED)
R21  ValueDisplayed: 11.0k  [0402]  (hidden comment: CRCW040211K0FKED)
R22  ValueDisplayed: 11.0k  [0402]  (hidden comment: CRCW040211K0FKED)
R23  ValueDisplayed: 24.9k  [0402]  (hidden comment: CRCW040224K9FKED)
TP1  5002  [Keystone5002]  (value not drawn)
TP2  5000  [Keystone5000]  (value not drawn)
TP3  5000  [Keystone5000]  (value not drawn)
TP4  5000  [Keystone5000]  (value not drawn)
TP5  5000  [Keystone5000]  (value not drawn)
TP6  5002  [Keystone5002]  (value not drawn)
TP7  5000  [Keystone5000]  (value not drawn)
TP8  5000  [Keystone5000]  (value not drawn)
TP9  5000  [Keystone5000]  (value not drawn)
TP10  5000  [Keystone5000]  (value not drawn)
TP11  5000  [Keystone5000]  (value not drawn)
TP12  5000  [Keystone5000]  (value not drawn)
TP14  5000  [Keystone5000]  (value not drawn)
U1  LM5150QRUMTQ1  [RUM0016C]
U2  LM74700QDBVTQ1  [DBV0006A_N]
U3  PartNumber: LM43602AQPWPRQ1  [PWP0016G_L]  (hidden comment: LM43602QPWPRQ1)
U4  LMR33630CQRNXRQ1  [RNX0012A]

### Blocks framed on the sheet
Reverse Battery Protection: C2 C8-C11 D2 L2 Q1 R8 TP3 TP4 U2
Pre-boost to 8.5V: C1 C3-C7 C12-C19 D1 L1 NTG1 Q2 R1-R7 R9-R13 TP1 TP2 TP5 TP6 U1
3V3 BUCK: C20-C27 C33 C34 C41 L3 R14-R17 R19 R22 TP12 U3
5V Buck: C28-C32 C35-C40 L4 R18 R20 R21 R23 TP14 U4

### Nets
3V3: C23.1 C24.1 C25.1 C26.1 C27.1 C34.1 L3.2 R16.2 R21.2 R22.2 TP12.1 U3.5(BIAS)
5V: C35.1 C36.1 C37.1 C38.1 C39.1 L4.2 R20.2 TP14.1
AGND: C13.2 C14.2 C15.2 C18.2 C19.2 NTG1.1 R10.1 R11.1 R12.1 U1.11(AGND)
GND: C2.2 C3.2 C4.2 C5.2 C6.2 C7.2 C8.2(-) C9.2 C10.2 C12.2 C16.2 C17.1 C20.2 C21.2 C23.2 C24.2 C25.2 C26.2 C29.2 C30.2 C31.2 C32.2 C33.1 C34.2 C35.2 C36.2 C37.2 C38.2 C40.2 C41.2 D2.1 J1.1 NTG1.2 R4.1 R17.1 R19.1 R23.1 TP7.1 TP8.1 TP9.1 TP10.1 TP11.1 U1.10(PGND) U1.17(EP) U2.2(GND) U3.6(SYNC) U3.10(AGND) U3.15(PGND) U3.16(PGND) U3.17(PAD) U4.1(PGND) U4.6(AGND) U4.11(PGND)
KL30_Power: C9.1 C10.1 C11.1 D2.2 J1.2 Q1.1(S) Q1.2(S) Q1.3(S) R8.1 TP3.1 U2.6(ANODE)
VBOOST: C3.1 C4.1 C5.1 C6.1 C7.1 C29.1 C30.1 C31.1 C32.1 D1.3(K) R1.2 R7.2 R18.2 TP2.1 U4.2(VIN) U4.10(VIN)
VIN: C8.1(+) C12.1 C13.1 L1.1 L2.2 R14.1 TP5.1 U1.16(VIN)
AVCC: C15.1 R9.1 U1.7(AVCC)
COMP: C18.1 R13.2 TP6.1 U1.13(COMP)
FB_3V3: C27.2 R16.1 R19.2 U3.9(FB)
FB_5V: C39.2 R20.1 R23.2 U4.7(FB)
P1.2_STA: U1.2(STATUS) ; off-sheet P1.2_STA
PG_3V3: R22.1 U3.8(PGOOD)
PG_5V: R21.1 U4.8(PG)
PVCC: C16.1 R9.2 U1.5(PVCC)
RT: R11.2 U1.14(RT)
VCC_5V: C40.1 U4.5(VCC)
Vout: C17.2 R5.1 R7.1 U1.4(VOUT)
VSET: R12.2 U1.15(VSET)
NetC1_1: C1.1 R1.1
NetC1_2: C1.2 D1.1(A) D1.2(A) L1.2 Q2.5(D) TP1.1
NetC2_1: C2.1 L2.1 Q1.5(D) Q1.6(D) Q1.7(D) Q1.8(D) Q1.9(D) TP4.1 U2.4(CATHODE)
NetC11_2: C11.2 U2.1(VCAP)
NetC14_1: C14.1 R3.1 R6.2
NetC19_1: C19.1 R13.1
NetC20_1: C20.1 C21.1 R14.2 R15.1 U3.13(VIN) U3.14(VIN)
NetC22_1: C22.1 U3.3(CBOOT)
NetC22_2: C22.2 L3.1 U3.1(SW) U3.2(SW)
NetC28_1: C28.1 U4.4(BOOT)
NetC28_2: C28.2 L4.1 U4.12(SW)
NetC33_2: C33.2 U3.4(VCC)
NetC41_1: C41.1 U3.11(SS/TRK)
NetQ1_4: Q1.4(G) U2.5(GATE)
NetQ2_1: Q2.1(S) Q2.2(S) Q2.3(S) R3.2 R4.2
NetQ2_4: Q2.4(G) R2.2
NetR2_1: R2.1 U1.9(LO)
NetR5_2: R5.2 U1.3(EN)
NetR6_1: R6.1 U1.12(CS)
NetR8_2: R8.2 U2.3(EN)
NetR10_2: R10.2 U1.1(SYNC)
NetR15_2: R15.2 U3.12(ENABLE)
NetR17_2: R17.2 U3.7(RT)
NetR18_1: R18.1 U4.9(EN)

Not connected (* = marked no-connect by the designer): U1 6(NC)* 8(NC)* A1(AP)* A2(AP)* A3(AP)* A4(AP)*; U4 3(NC)*

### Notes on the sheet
- R6 optional for the slope compensation
- floating 4.1ms

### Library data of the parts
C1 = CMP-0006357-2: CAP, CERM, 2200 pF, 50 V, +/- 10%, X7R, AEC-Q200 Grade 1, 0402; Manufacturer: MuRata; PartNumber: GCM155R71H222KA37D; TaMin_C: -55°C; Polarized: N; SizeAreaWB_mm2: 3; Value1: Unknown; U/M: EA; Value: 2200pF; TaMax_C: 125°C; SizeZ_mm: 0.6; SizeX_mm: 1; SizeY_mm: 0.5; Value2: 50V; CompType: Capacitor; AEC Qualified: Y; Cap_F: 2.2nF; AEC Category: Q200
C2-C6 C9 C12 C20 C29 C31 = CMP-0009258-2: CAP, CERM, 10 uF, 50 V, +/- 10%, X7R, AEC-Q200 Grade 1, 1210; Manufacturer: Taiyo Yuden; TaMin_C: -55°C; Polarized: N; SizeAreaWB_mm2: 14.7; Value1: Unknown; U/M: EA; Value: 10uF; TaMax_C: 125°C; SizeZ_mm: 2.8; SizeX_mm: 3.2; SizeY_mm: 2.5; Cap_Case: 1210; Value2: 50V; SizeArea_mm2: 8; CompType: Capacitor; AEC Qualified: Y; Cap_F: 10µF; AEC Grade: 1; AEC Category: Q200
C7 C10 C13 C15 C21 C28 C37 C38 = CMP-0006356-2: as C42 on sheet TIDA01628_Telltale
C8 = CMP-0011177-2: CAP, AL, 100 uF, 50 V, +/- 20%, 0.34 ohm, AEC-Q200 Grade 2, SMD; Manufacturer: Panasonic; TaMin_C: -55°C; ESR_ohm: 3.4d; Polarized: Y; SizeAreaWB_mm2: 123.6; U/M: EA; Value: 100uF; TaMax_C: 105°C; SizeZ_mm: 10.2; SizeX_mm: 10; SizeY_mm: 8.3; Cap_Case: F; Value2: 50V; SizeArea_mm2: 83; CompType: Capacitor; Cap_F: 100µF; IRMS_A: 3.5dA; AEC Grade: 2; AEC Category: Q200
C11 = C2012X5R1H225K125AB: CAP, CERM, 2.2 µF, 50 V, +/- 10%, X5R, 0805; Manufacturer: TDK; CompType: Capacitor; Value: 2.2uF; Polarized: N; U/M: EA; Cap_F: 0.0000022; Tolerance_%: 10; Value1: Unknown; VDC_V: 50; Value2: 50V; TaMin_C: -55; TaMax_C: 85; Cap_Case: 0805
C14 = CMP-0006673-2: CAP, CERM, 1000 pF, 50 V, +/- 10%, X7R, 0402; Manufacturer: MuRata; TaMin_C: -55°C; Polarized: N; SizeAreaWB_mm2: 3; Value1: Unknown; U/M: EA; Value: 1000pF; TaMax_C: 125°C; SizeZ_mm: 0.6; SizeX_mm: 1; SizeY_mm: 0.5; Value2: 50V; CompType: Capacitor; Cap_F: 1nF; AEC Category: Q200
C16 C33 = CMP-0008019-2: as C43 on sheet TIDA01628_Telltale
C17 C34 C40 = CMP-0007136-5: as C49 on sheet TIDA01628_Telltale
C18 = CMP-0006310-2: CAP, CERM, 150 pF, 50 V, +/- 5%, C0G/NP0, AEC-Q200 Grade 1, 0402; Manufacturer: TDK; TaMin_C: -55°C; Polarized: N; SizeAreaWB_mm2: 3; Value1: Unknown; U/M: EA; Value: 150pF; TaMax_C: 125°C; SizeZ_mm: 0.6; SizeX_mm: 1; SizeY_mm: 0.5; Value2: 50V; CompType: Capacitor; AEC Qualified: Y; AEC Category: Q200
C19 = CMP-0006321-2: CAP, CERM, 4700 pF, 50 V, +/- 10%, X7R, AEC-Q200 Grade 1, 0402; Manufacturer: TDK; TaMin_C: -55°C; ESR_ohm: 4.13508d; Polarized: N; SizeAreaWB_mm2: 3; Value1: 0.413508 ohm; U/M: EA; Value: 4700pF; TaMax_C: 125°C; SizeZ_mm: 0.6; SizeX_mm: 1; SizeY_mm: 0.5; Value2: 50V; CompType: Capacitor; AEC Qualified: Y; Cap_F: 4.7nF; IRMS_A: 3.30878dA; AEC Category: Q200
C22 C27 C30 C32 = CMP-0007094-5: CAP, CERM, 0.22 uF, 50 V, +/- 10%, X7R, AEC-Q200 Grade 1, 0603; Manufacturer: TDK; TaMin_C: -55°C; ESR_ohm: 0.021699; Polarized: N; SizeAreaWB_mm2: 4.68; Value1: 0.021699 ohm; U/M: EA; Value: 0.22uF; TaMax_C: 125°C; SizeZ_mm: 1; SizeX_mm: 1.6; SizeY_mm: 0.8; Value2: 50V; SizeArea_mm2: 1.28; CompType: Capacitor; AEC Qualified: Y; Cap_F: 220nF; IRMS_A: 1.12496A; AEC Category: Q200
C23-C25 C35 C36 = CMP-0009154-2: CAP, CERM, 22 uF, 16 V, +/- 20%, X7R, AEC-Q200 Grade 1, 1210; Manufacturer: TDK; TaMin_C: -55°C; ESR_ohm: 2.582m; Polarized: N; SizeAreaWB_mm2: 14.7; Value1: 0.002582 ohm; U/M: EA; Value: 22uF; TaMax_C: 125°C; SizeZ_mm: 2.8; SizeX_mm: 3.2; SizeY_mm: 2.5; Value2: 16V; SizeArea_mm2: 8; CompType: Capacitor; AEC Qualified: Y; Cap_F: 22µF; IRMS_A: 4.57562A; AEC Grade: 1; AEC Category: Q200
C26 C39 = CMP-0006324-2: CAP, CERM, 0.01 uF, 50 V, +/- 10%, X7R, AEC-Q200 Grade 1, 0402; Manufacturer: TDK; TaMin_C: -55°C; ESR_ohm: 3.33065d; Polarized: N; SizeAreaWB_mm2: 3; Value1: 0.333065 ohm; U/M: EA; Value: 0.01uF; TaMax_C: 125°C; SizeZ_mm: 0.6; SizeX_mm: 1; SizeY_mm: 0.5; Value2: 50V; CompType: Capacitor; AEC Qualified: Y; Cap_F: 10nF; IRMS_A: 3.23373dA; AEC Category: Q200
C41 = CMP-0006327-2: CAP, CERM, 0.015 uF, 50 V, +/- 10%, X7R, AEC-Q200 Grade 1, 0402; Manufacturer: TDK; TaMin_C: -55°C; ESR_ohm: 2.162d; Polarized: N; SizeAreaWB_mm2: 3; Value1: 0.2162 ohm; U/M: EA; TaMax_C: 125°C; SizeZ_mm: 0.6; SizeX_mm: 1; SizeY_mm: 0.5; Value2: 50V; CompType: Capacitor; AEC Qualified: Y; Cap_F: 15nF; IRMS_A: 3.79389dA; AEC Category: Q200
D1 = CMP-0028903-1: Diode, Schottky, 60 V, 10 A, AEC-Q101, TO-277A; Manufacturer: Vishay-Semiconductor; Io_A: 10A; Green_Lifecycle: Not Set; SizeAreaWB_mm2: 57.375; Vr_V: 60V; Green_REACh: Incomplete; TJmax_C: 150°C; U/M: EA; Value: 60V; SizeZ_mm: 1.2; SizeX_mm: 6.5; SizeY_mm: 4.75; Vf_V: 5.9dV; Value2: 0.59V; SizeArea_mm2: 30.875; AEC Qualified: Y; AEC Category: Q101
D2 = CMP-0005564-2: Diode, TVS, Bi, 33 V, SMB; Manufacturer: Diodes Inc.; Power_W: 5W; SizeAreaWB_mm2: 44.156; U/M: EA; SizeZ_mm: 2.6; SizeX_mm: 5.6; SizeY_mm: 3.81; SizeArea_mm2: 21.336; AEC Category: Q101
J1 = CMP-0055551-1: Header (Shrouded), 5.08mm, 2x1, Tin, R/A, TH; Manufacturer: Phoenix Contact; Cert_VDE: Y; CNHeader: FALSE; Current_A: 12A; Green_Lifecycle: Not Set; Gender: Male; Green_REACh: Incomplete; Voltage_V: 400V; Row_Count: 1; Pitch_mm: 5.08
L1 = CMP-0061081-1: Inductor, Shielded, Composite, 560 nH, 11.3 A, 0.008 ohm, AEC-Q200 Grade 1, SMD; Manufacturer: Coilcraft; Isat: 11.3A @ 30% inductance drop; Irms: 13.8A @ 40C rise; SizeAreaWB_mm2: 25; DCR_ohm: 8m; Value: 560nH; Imax_A: 11.3A; SizeZ_mm: 2.1; SizeX_mm: 4; SizeArea_mm2: 16; AEC Qualified: Y; AEC Grade: 1; AEC Category: Q200
L2 = CMP-0064228-1: Inductor, Shielded Drum Core, Ferrite, 1 uH, 4 A, 0.049 ohm, SMD; Manufacturer: Wurth Elektronik; Isat: 5.72A @ 10% inductance drop; Irms: 4A @ 40C rise; Green_Lifecycle: Active; SizeAreaWB_mm2: 27.5; DCR_ohm: 0.049; Green_REACh: Passed; Value: 1uH; Imax_A: 4A; SizeZ_mm: 3.2; SizeX_mm: 4; SizeY_mm: 4.5; SizeArea_mm2: 18; Ind_H: 1µH; AEC Category: Q200
L3 = CMP-0063808-1: Inductor, Shielded Drum Core, Ferrite, 1.8 uH, 2.45 A, 0.02 ohm, SMD; Manufacturer: Wurth Elektronik; Isat: 2.45A @ 35% inductance drop; Irms: 2.7A @ 30C rise; Green_Lifecycle: Active; SizeAreaWB_mm2: 33.64; DCR_ohm: 0.02; Green_REACh: Passed; Value: 1.8uH; Imax_A: 2.45A; SizeZ_mm: 3; SizeX_mm: 4.8; SizeArea_mm2: 23.04; Ind_H: 1.8µH; AEC Category: Q200
L4 = CMP-0064214-1: Inductor, Shielded Drum Core, Ferrite, 1.5 uH, 6.2 A, 0.0137 ohm, SMD; Manufacturer: Wurth Elektronik; Isat: 9.5A @ 10% inductance drop; Irms: 6.2A @ 40C rise; Green_Lifecycle: Active; SizeAreaWB_mm2: 144; DCR_ohm: 0.0137; Green_REACh: Passed; Value: 1.5uH; Imax_A: 6.2A; SizeZ_mm: 3; SizeX_mm: 10; SizeArea_mm2: 100; Ind_H: 1.5µH; AEC Category: Q200
NTG1 = Net-Tie: Single point connection between nets.; SymbolCreator: codlsc
Q1 = CMP-0067553-1: MOSFET, N-CH, 60 V, 15 A, AEC-Q101, 8-PowerVDFN; Alternate Manufacturer: None; Manufacturer: Diodes Inc.; Rdson45_ohm: 8.5m; QgTyp_nC: 41.3; SizeAreaWB_mm2: 18.49; Vgs_V: 20V; Value1: 0.0085 ohm; VdsMax_V: 60V; U/M: EA; Value: 60V; IdsMax_A: 15A; SizeZ_mm: 0.8; SizeX_mm: 3.3; Value2: 41.3 nC; SizeArea_mm2: 10.89; ChType: N; AEC Qualified: Y; AEC Category: Q101
Q2 = CMP-0000806-1: MOSFET, N-CH, 60 V, 12.8 A, AEC-Q101, 3.4x0.9x2.7mm; Alternate Manufacturer: None; Manufacturer: NXP Semiconductor; SizeZ_mm: 0.9; ChType: N; Value2: 4.4 nC; VdsMax_V: 60V; SizeX_mm: 3.3; Vgs_V: 10V; QgTyp_nC: 4.4; AEC Qualified: Y; Value: 60V; SizeArea_mm2: 10.89; AEC Category: Q101; IdsMax_A: 12.8A; SizeAreaWB_mm2: 18.49; U/M: EA
R1 = CMP-0016110-3: RES, 2.0, 5%, 0.75 W, AEC-Q200 Grade 0, 2010; Manufacturer: Vishay-Dale; PartNumber: CRCW20102R00JNEF; Power_W: 750mW; TempCo: 200 ppm/C; Value_Code: 2R00; Value: 2.0; EIA_Code: E24; Res_ohm: 2; SizeX_mm: 5; SizeY_mm: 2.5; SizeZ_mm: 1.66; Value2: 0.75W; SizeArea_mm2: 12.5; CompType: Resistor; AEC Qualified: Y; VDC_V: 400V; AEC Grade: 0; AEC Category: Q200
R2 R5 R6 R8 R10 R15 R18 = CMP-0026822-3: RES, 0, 5%, 0.063 W, AEC-Q200 Grade 0, 0402; Manufacturer: Vishay-Dale; Power_W: 63mW; TempCo: 200 ppm/C; Value_Code: 0000; Value: 0; EIA_Code: E24; SizeX_mm: 1; SizeY_mm: 0.5; SizeZ_mm: 0.6; Value2: 0.063W; AEC Qualified: Y; VDC_V: 50V; AEC Category: Q200
R3 = CMP-0026404-2: RES, 49.9, 1%, 0.063 W, AEC-Q200 Grade 0, 0402; Manufacturer: Vishay-Dale; Power_W: 63mW; TempCo: 100 ppm/C; Value_Code: 49R9; Value: 49.9; EIA_Code: E96; SizeX_mm: 1; SizeY_mm: 0.5; SizeZ_mm: 0.6; Value2: 0.063W; AEC Qualified: Y; VDC_V: 50V; AEC Category: Q200; AEC Grade: 0
R4 = CMP-0018571-2: RES, 0.015, 1%, 1 W, 1206; Manufacturer: Vishay-Dale; Power_W: 1W; TempCo: 75 ppm/C; Value_Code: R015; U/M: EA; Value: 0.015; EIA_Code: E96; SizeX_mm: 3.2; SizeY_mm: 1.6; SizeZ_mm: 1.35; SizeArea_mm2: 5.12; AEC Category: Q200
R7 = CMP-0023011-2: RES, 2.00, 1%, 0.1 W, 0603; Manufacturer: Yageo America; Power_W: 100mW; TempCo: 200 ppm/C; Value_Code: 2R00; U/M: EA; Value: 2.00; EIA_Code: E96; Res_ohm: 2; SizeX_mm: 1.6; SizeY_mm: 0.8; SizeZ_mm: 1; Value2: 0.1W; SizeArea_mm2: 1.28; VDC_V: 150V; AEC Category: Q200
R9 = CMP-0025963-3: RES, 10.0, 1%, 0.063 W, AEC-Q200 Grade 0, 0402; Manufacturer: Vishay-Dale; Power_W: 63mW; TempCo: 100 ppm/C; Value_Code: 10R0; Value: 10.0; EIA_Code: E96; Res_ohm: 10; SizeX_mm: 1; SizeY_mm: 0.5; SizeZ_mm: 0.6; Value2: 0.063W; AEC Qualified: Y; VDC_V: 50V; AEC Category: Q200; AEC Grade: 0
R11 R12 = CMP-0022667-4: RES, 9.53 k, 1%, 0.1 W, AEC-Q200 Grade 0, 0603; Manufacturer: Vishay-Dale; Power_W: 100mW; TempCo: 100 ppm/C; Value_Code: 9k53; Value: 9.53k; EIA_Code: E96; SizeX_mm: 1.6; SizeY_mm: 0.8; SizeZ_mm: 1; Value2: 0.1W; SizeArea_mm2: 1.28; AEC Qualified: Y; VDC_V: 75V; AEC Category: Q200; AEC Grade: 0
R13 = CMP-0026405-2: RES, 4.02 k, 1%, 0.063 W, AEC-Q200 Grade 0, 0402; Manufacturer: Vishay-Dale; Power_W: 63mW; TempCo: 100 ppm/C; Value_Code: 4k02; Value: 4.02k; EIA_Code: E96; SizeX_mm: 1; SizeY_mm: 0.5; SizeZ_mm: 0.6; Value2: 0.063W; AEC Qualified: Y; VDC_V: 50V; AEC Category: Q200; AEC Grade: 0
R14 = CMP-0018573-3: RES, 0, 5%, 0.25 W, AEC-Q200 Grade 0, 1206; Manufacturer: Vishay-Dale; Power_W: 250mW; TempCo: 200 ppm/C; Value_Code: 0000; Value: 0; EIA_Code: E24; SizeX_mm: 3.2; SizeY_mm: 1.6; SizeZ_mm: 1.35; Value2: 0.25W; SizeArea_mm2: 5.12; AEC Qualified: Y; VDC_V: 200V; AEC Category: Q200
R16 R20 = CMP-0025950-3: RES, 100 k, 1%, 0.063 W, AEC-Q200 Grade 0, 0402; Manufacturer: Vishay-Dale; Power_W: 63mW; TempCo: 100 ppm/C; Value: 100k; EIA_Code: E96; SizeX_mm: 1; SizeY_mm: 0.5; SizeZ_mm: 0.6; Value2: 0.063W; AEC Qualified: Y; VDC_V: 50V; AEC Category: Q200; AEC Grade: 0
R17 = CMP-0026058-3: RES, 18.0 k, 1%, 0.063 W, AEC-Q200 Grade 0, 0402; Manufacturer: Vishay-Dale; Power_W: 63mW; TempCo: 100 ppm/C; Value_Code: 18k0; Value: 18.0k; Res_ohm: 18k; SizeX_mm: 1; SizeY_mm: 0.5; SizeZ_mm: 0.6; Value2: 0.063W; AEC Qualified: Y; VDC_V: 50V; AEC Grade: 0; AEC Category: Q200
R19 = CMP-0026379-2: RES, 43.2 k, 1%, 0.063 W, AEC-Q200 Grade 0, 0402; Manufacturer: Vishay-Dale; Power_W: 63mW; TempCo: 100 ppm/C; Value_Code: 43k2; Value: 43.2k; EIA_Code: E96; SizeX_mm: 1; SizeY_mm: 0.5; SizeZ_mm: 0.6; Value2: 0.063W; AEC Qualified: Y; VDC_V: 50V; AEC Category: Q200; AEC Grade: 0
R21 R22 = CMP-0025975-3: RES, 11.0 k, 1%, 0.063 W, AEC-Q200 Grade 0, 0402; Manufacturer: Vishay-Dale; Power_W: 63mW; TempCo: 100 ppm/C; Value_Code: 11k0; Value: 11.0k; EIA_Code: E96; Res_ohm: 11k; SizeX_mm: 1; SizeY_mm: 0.5; SizeZ_mm: 0.6; Value2: 0.063W; AEC Qualified: Y; VDC_V: 50V; AEC Category: Q200; AEC Grade: 0
R23 = CMP-0026196-2: RES, 24.9 k, 1%, 0.063 W, AEC-Q200 Grade 0, 0402; Manufacturer: Vishay-Dale; Power_W: 63mW; TempCo: 100 ppm/C; Value_Code: 24k9; Value: 24.9k; EIA_Code: E96; SizeX_mm: 1; SizeY_mm: 0.5; SizeZ_mm: 0.6; Value2: 0.063W; AEC Qualified: Y; VDC_V: 50V; AEC Category: Q200; AEC Grade: 0
TP1 TP6 = CMP-0055139-1: as TP15 on sheet TIDA01628_Telltale
TP2-TP5 TP7-TP12 TP14 = CMP-0055137-1: Test Point, Miniature, Red, TH; Manufacturer: Keystone; CNHeader: FALSE; Green_Lifecycle: Active; Green_REACh: Passed; ContactFinish: Silver; CT: TRUE
U1 = CMP-0078203-1: Wide VIN Automotive Low IQ Boost Controller, RUM0016C (WQFN-16); Alternate PartNumber: LM5150QRUMRQ1; Alternate Manufacturer: Texas Instruments; SizeAreaWB_mm2: 25; SizeZ_mm: 0.8; SizeX_mm: 4; SizeArea_mm2: 16; CompType: IC; AEC Qualified: Y; AEC Category: Q200
U2 = CMP-0079180-1: Low Iq Always ON Smart Diode Controller, DBV0006A (SOT-23-6); Alternate PartNumber: LM74700QDBVRQ1; Alternate Manufacturer: Texas Instruments; SizeAreaWB_mm2: 14.82; SizeZ_mm: 1.45; SizeX_mm: 2.8; SizeY_mm: 2.9; SizeArea_mm2: 8.12; CompType: IC; AEC Qualified: Y; AEC Category: Q200
U3 = CMP-0076311-2: Automotive Qualified SIMPLE SWITCHER(R) 3.5V to 36V, 2A Synchronous Step-Down Voltage Converter, PWP0016G (TSSOP-16); Alternate PartNumber: LM43602AQPWPTQ1; Manufacturer: Texas Instruments; SizeZ_mm: 1.2; SizeX_mm: 6.4; SizeY_mm: 5.0; SizeArea_mm2: 32.0; CompType: IC; U/M: EA; SizeAreaWB_mm2: 58.8
U4 = CMP-0078599-1: SIMPLE SWITCHER 3.8-V to 36-V 3-A Synchronous Step-Down Voltage Regulator, RNX0012A (VQFN-HR-12); Alternate PartNumber: LMR33630CQRNXTQ1; Alternate Manufacturer: Texas Instruments; SizeAreaWB_mm2: 9; SizeZ_mm: 1; SizeX_mm: 2; SizeArea_mm2: 4; CompType: IC; AEC Qualified: Y; AEC Category: Q200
